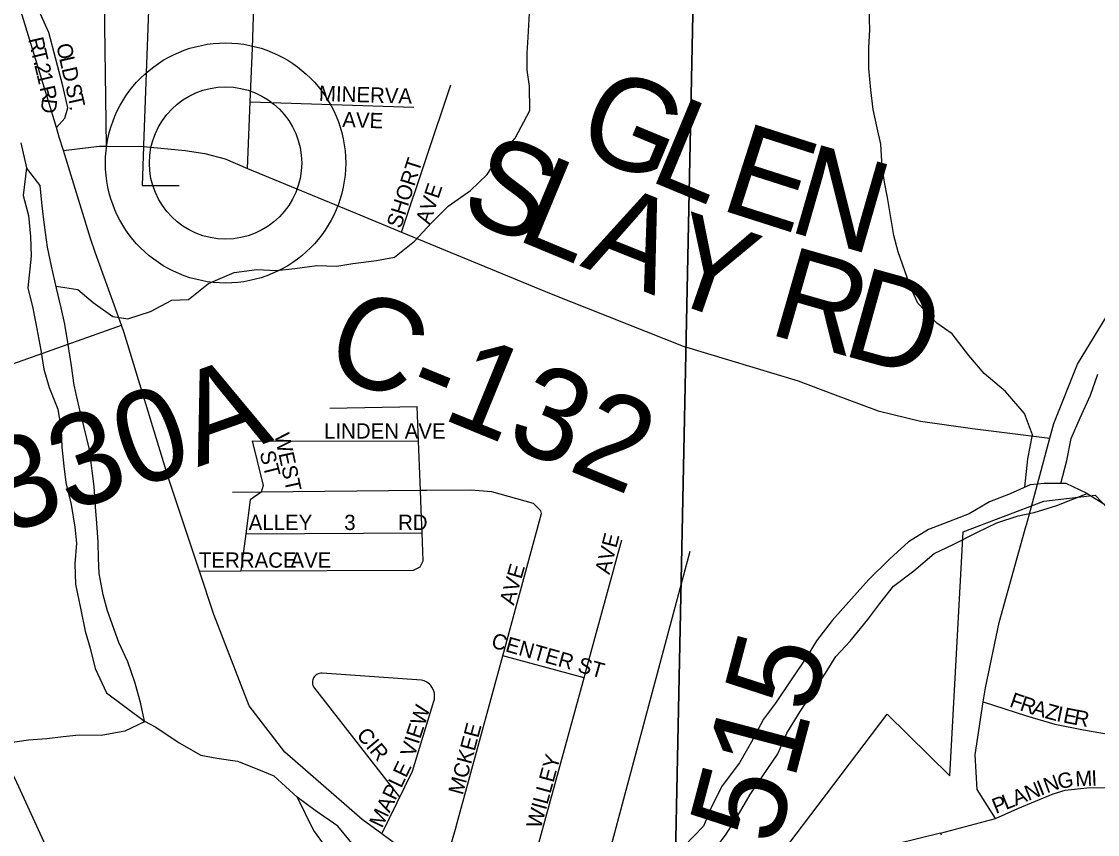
# Model space of a CAD drawing. Extents: x 2043100 to 2470832, y 443715 to 810583.
# Drawn here: x 2240142 to 2243660, y 639483 to 642142 of the extents above; entities that cross this region are included whole.
import ezdxf

# ---------------------------------------------------------------- set-up
doc = ezdxf.new("R2010")
doc.units = 0
for name, color, linetype in [('GM_X_City_Street', 7, 'Continuous'), ('GM_X_City_Street_Text', 7, 'Continuous'), ('GM_X_Corporation', 7, 'Continuous'), ('GM_X_County_Road', 7, 'Continuous'), ('GM_X_County_Road_Text', 7, 'Continuous'), ('GM_X_Interstate_Route', 7, 'Continuous'), ('GM_X_Major_River', 7, 'Continuous'), ('GM_X_Minor_River', 7, 'Continuous'), ('GM_X_Section', 7, 'Continuous'), ('GM_X_State_Route', 7, 'Continuous'), ('GM_X_Township_Road', 7, 'Continuous'), ('GM_X_Township_Road_Text', 7, 'Continuous'), ('GM_X_Township_Subdivision', 7, 'Continuous'), ('GM_X_Township_Subdivision_Text', 7, 'Continuous'), ('GM_X_Unincorporated', 7, 'Continuous'), ('GM_X_Unincorporated_Location', 7, 'Continuous')]:
    doc.layers.add(name, color=color, linetype=linetype)

msp = doc.modelspace()

# ---------------------------------------------------------------- linework, layer by layer
at = {"layer": 'GM_X_City_Street'}
for points in [[(2243286.7, 639917.5), (2243427.8, 639871.2), (2243520.1, 639844.4), (2243614.3, 639825.7), (2243753.1, 639801.8), (2244056.4, 639793.6), (2244190.2, 639793.3), (2244301.9, 639785.7), (2244380.2, 639763.3), (2244436.7, 639738.5), (2244587.8, 639642.4), (2244776.1, 639523.2)], [(2243326.2, 639536.1), (2243399.7, 639568.6), (2243515, 639616.2), (2243554.8, 639628.7), (2243624.7, 639635.6), (2243748.2, 639637.1)]]:
    msp.add_lwpolyline(points, dxfattribs=at)
at = {"layer": 'GM_X_Corporation'}
msp.add_lwpolyline([(2242944.3, 637149), (2242931.5, 637610.5), (2240814.2, 637621.4), (2240814.2, 638839.3), (2242113.9, 638816.9), (2242623.4, 639416.8), (2242972.5, 639877.1), (2243176.9, 639675.1), (2243220.7, 640473.4), (2243485, 640573.3), (2243652.8, 640592.9), (2243759.2, 640481)], dxfattribs=at)
at = {"layer": 'GM_X_County_Road'}
msp.add_lwpolyline([(2240278.9, 641720.1), (2240395.4, 641734.2), (2240419.4, 641734.3), (2240540.7, 641733.6), (2240677.3, 641720.6), (2240741.3, 641710.7), (2240807.3, 641692.8), (2240881.3, 641662.1), (2241235.3, 641515.2), (2241384.7, 641453.5), (2241873.3, 641251.9), (2242305.3, 641080.3), (2242681.2, 640966.7), (2242793.2, 640924.9), (2242943.2, 640869), (2243081.2, 640835.2), (2243251.2, 640811.4), (2243504.2, 640779.5)], dxfattribs=at)
at = {"layer": 'GM_X_Interstate_Route'}
msp.add_lwpolyline([(2240394.7, 638771), (2240382.5, 638881.1), (2240303.2, 639267.5), (2240121.4, 639665.5), (2239921.6, 640061.4), (2239486.5, 640666.7), (2238945.3, 641275.5), (2238484.4, 641836.6), (2237995, 642501.7), (2237789.2, 642869.6), (2237609.2, 643317.8), (2237341.9, 644058.2), (2237167.9, 644510.4), (2236925.2, 645114.6), (2236607.5, 645943), (2236281.8, 646755.3), (2236081.5, 647271.5), (2235837.1, 647771.5), (2235579.2, 648157.2), (2235141.7, 648882.8), (2234805.3, 649336.2), (2234488.5, 649938.1), (2234352.9, 650290.3), (2234278.2, 650792.6)], dxfattribs=at)
at = {"layer": 'GM_X_Major_River'}
for points in [[(2240139.7, 641745.3), (2240158.6, 641663.4)], [(2240158.6, 641663.4), (2240147.5, 641573.2), (2240164.2, 641507.4), (2240170.9, 641439.4), (2240173.5, 641375.4), (2240162.6, 641271.2), (2240179.2, 641205.3), (2240191.9, 641137.4), (2240204.6, 641067.5), (2240215.3, 641005.6), (2240231.9, 640945.7), (2240260.6, 640874), (2240271.3, 640808), (2240273.9, 640750), (2240280.5, 640688.1), (2240287, 640634.1), (2240303.8, 640562.2), (2240316.5, 640488.3), (2240321.1, 640436.3), (2240315.7, 640368.2), (2240318.4, 640302.2), (2240335.3, 640218.3), (2240350, 640148.4), (2240366.6, 640092.6), (2240383.2, 640026.7), (2240420, 639947.1), (2240543.9, 639853.9)], [(2240543.9, 639853.9), (2240532.4, 639910.2), (2240513.7, 639978.1), (2240489, 640047.9), (2240460.3, 640111.6), (2240423.3, 640215.3), (2240408.8, 640267.2), (2240396, 640337.1), (2240393.5, 640387.1), (2240393, 640439.1), (2240388.4, 640501.1), (2240383.8, 640555.1), (2240379.1, 640621.1), (2240372.6, 640673.1), (2240363.9, 640743), (2240347.2, 640814.9), (2240330.5, 640880.8), (2240313.8, 640952.6), (2240305.1, 641016.6), (2240294.4, 641086.5), (2240283.7, 641152.4), (2240271.2, 641206.3), (2240256.6, 641270.2), (2240239.8, 641342.1), (2240227.2, 641404), (2240216.5, 641475.9), (2240209.8, 641539.9), (2240203.1, 641605.9), (2240158.6, 641663.4)], [(2243626.2, 640598.5), (2243557.9, 640631.8), (2243485.2, 640631.8), (2243440, 640626.5), (2243374.3, 640597.7), (2243306.6, 640571), (2243241, 640532.2), (2243173.3, 640505.5), (2243107.6, 640480.7), (2243042, 640440), (2242980.6, 640385.3), (2242911.3, 640316.5), (2242856, 640253.8), (2242792.8, 640183.1), (2242741.5, 640116.5), (2242710, 640064.1), (2242658.8, 639989.5), (2242607.6, 639912.9), (2242568.1, 639860.4), (2242528.9, 639785.9), (2242489.6, 639717.5), (2242432.4, 639642.8), (2242399.1, 639576.4), (2242371.8, 639510), (2242308.5, 639445.3)], [(2242400.7, 639424.3), (2242446, 639484.8), (2242481.4, 639541.2), (2242524.7, 639613.8), (2242564.1, 639672.2), (2242615.3, 639746.8), (2242644.6, 639815.2), (2242687.8, 639885.8), (2242737.1, 639958.3), (2242770.5, 640010.7), (2242804, 640065.1), (2242851.4, 640115.7), (2242908.7, 640186.4), (2242948.1, 640238.8), (2242993.5, 640295.4), (2243059, 640346.1), (2243126.4, 640402.9), (2243188.1, 640431.6), (2243267.6, 640472.5), (2243331.3, 640503.2), (2243401, 640526), (2243452.9, 640536.5), (2243526.7, 640559.4), (2243626.2, 640598.5)], [(2243626.2, 640598.5), (2243692.6, 640557.2), (2243751.2, 640499.8), (2243811.8, 640442.4), (2243862.1, 640404.9), (2243914.2, 640393.5)], [(2240543.9, 639853.9), (2240581.1, 639834.7), (2240657.6, 639783.5), (2240728, 639742.3), (2240780.1, 639732.8), (2240848.1, 639723.6), (2240916.4, 639696.3), (2240966.6, 639674.8), (2241043.3, 639605.6)], [(2241043.3, 639605.6), (2241096.4, 639496.1), (2241134.9, 639444.5)], [(2241232.9, 639441.6), (2241176.2, 639511), (2241101.7, 639562.2), (2241043.3, 639605.6)]]:
    msp.add_lwpolyline(points, dxfattribs=at)
at = {"layer": 'GM_X_Minor_River'}
for points in [[(2243423, 640619), (2243432.2, 640711.9), (2243448, 640790), (2243421.8, 640860), (2243359.6, 640931.8), (2243289.4, 640991.6), (2243239.3, 641049.5), (2243185.1, 641121.3), (2243135, 641155.2), (2243072.8, 641221), (2243048.7, 641273), (2243030.5, 641326.9), (2243008.4, 641388.9), (2242994.2, 641442.9), (2242984, 641500.9), (2242973.8, 641566.9), (2242963.7, 641616.9), (2242955.5, 641666.9), (2242951.3, 641741), (2242939.2, 641795), (2242927, 641855), (2242918.8, 641919), (2242912.6, 641989), (2242912.4, 642057.1), (2242916.2, 642115.1), (2242914, 642185.2)], [(2240255.1, 641276.6), (2240325.8, 641265.6), (2240375.9, 641223.7), (2240440, 641177.9), (2240490, 641170.1), (2240563.9, 641194.4), (2240633.8, 641230.6), (2240687.7, 641232.8), (2240753.6, 641285.1), (2240837.4, 641321.4), (2240911.4, 641331.7), (2240975.3, 641327.9), (2241035.3, 641334.1), (2241107.2, 641344.3), (2241173.2, 641342.6), (2241225.2, 641350.8), (2241303.1, 641361), (2241361.1, 641371.2), (2241426.9, 641423.5), (2241482.7, 641483.7), (2241536.5, 641538), (2241610.3, 641590.2), (2241664.1, 641642.5), (2241698, 641694.6), (2241755.7, 641760.9), (2241803.5, 641851.1), (2241803.2, 641931.2), (2241795.1, 641983.2), (2241794.9, 642039.2), (2241798.7, 642091.3), (2241802.5, 642169.3)], [(2243540.3, 640631.8), (2243560.2, 640706.3), (2243573.9, 640778.4), (2243603.7, 640846.6), (2243637.5, 640920.7), (2243661.3, 640988.9)], [(2240546.6, 639852.5), (2240480.1, 639821.1), (2240402.1, 639806.8), (2240330.2, 639808.5), (2240278.2, 639802.4), (2240224.2, 639796.2), (2240164.3, 639792), (2240098.3, 639781.7)]]:
    msp.add_lwpolyline(points, dxfattribs=at)
at = {"layer": 'GM_X_Section'}
for points in [[(2242378.2, 644174.8), (2242269, 638887.7), (2242088.5, 638885.8), (2236986.2, 638960.8), (2237095.6, 644222)], [(2247636.8, 644123.4), (2247507.7, 638791.7), (2242269, 638887.7), (2242378.2, 644174.8)]]:
    msp.add_lwpolyline(points, close=True, dxfattribs=at)
at = {"layer": 'GM_X_State_Route'}
for points in [[(2240384.2, 641385), (2240367.1, 641432.7), (2240278.9, 641720.1), (2240265.4, 641764.1), (2240255.7, 641796.2), (2240129.1, 642214.4), (2239996.8, 642598.6), (2239934.5, 642755.4), (2239884.6, 642880.8), (2239654.4, 643240.8), (2239542.3, 643362.8), (2239348.2, 643548.7), (2239224.2, 643672.7), (2238711.9, 644192.5), (2238530.6, 644495.1), (2238493.7, 644556.6), (2238411.1, 644745.2), (2238269.4, 645068.8), (2238174.6, 645363.4), (2238086.8, 645787.4), (2237986.4, 646321.9), (2237949.9, 646434.6), (2237924.3, 646608.8)], [(2243427.3, 640494.3), (2243427.8, 640496), (2243447.7, 640567.6), (2243504.2, 640779.5), (2243517, 640827.8), (2243594.9, 641022.1), (2243746.6, 641270.6), (2243823.2, 641405.3), (2243897.3, 641485.5)], [(2241707.1, 639276.8), (2241672.9, 639289.4), (2241519.2, 639358.5), (2241446.4, 639391.3), (2241319.8, 639485.2), (2241255.9, 639532.6), (2241002.8, 639752.9), (2240885.8, 639903.7), (2240770.5, 640203.1), (2240723.5, 640344.6), (2240622.2, 640649.3), (2240477.8, 641123.7), (2240468.9, 641148.8), (2240384.2, 641385)], [(2243146.3, 639487.8), (2243326.2, 639536.1), (2243266.1, 639630.1), (2243260, 639744.2), (2243286.7, 639917.5), (2243293.7, 639963.5), (2243339, 640176.2), (2243427.3, 640494.3)], [(2243149.7, 639480.8), (2243146.3, 639487.8), (2242933.7, 639435.4), (2242868.4, 639419.3), (2242834.4, 639417.2), (2242825.2, 639418.8), (2242716.5, 639437.1), (2242617.1, 639441.3), (2242579.7, 639442.8)]]:
    msp.add_lwpolyline(points, dxfattribs=at)
at = {"layer": 'GM_X_Township_Road'}
for points in [[(2239548.4, 640822), (2240468.9, 641148.8)], [(2242004.5, 639200.5), (2242328.2, 640409.5)]]:
    msp.add_lwpolyline(points, dxfattribs=at)
at = {"layer": 'GM_X_Township_Subdivision'}
for points in [[(2240881.3, 641662.1), (2240889.9, 641879.4), (2240896.9, 642055.3), (2240901.8, 642193.5), (2240913.6, 642525.3), (2240924.9, 642845.7), (2240916.2, 642998.4), (2240858.2, 643197.8), (2240800, 643302.6), (2240712.6, 643436), (2240583.8, 643632.6), (2240577.7, 643660.7), (2240581.7, 643680.7), (2240617.7, 643706.8), (2240845.6, 643771.2), (2240953.5, 643781.4), (2241073.5, 643763.5)], [(2240255.7, 641796.2), (2240283.3, 641826.2), (2240293.3, 641860.2), (2240277.2, 641932.3), (2240231.1, 642106.4), (2240205.1, 642164.4), (2240191, 642202.8), (2240179, 642272.5), (2240186.8, 642572.9), (2240193, 642845.1)], [(2240419.4, 641734.3), (2240413.1, 642206.8), (2240404.5, 642859.4)], [(2240582.4, 642851.9), (2240558.4, 642209.4), (2240540.9, 641738.1)], [(2241384.7, 641453.5), (2241546, 641935.4)], [(2240889.9, 641879.4), (2241424.9, 641861.9)], [(2240540.9, 641738.1), (2240540.7, 641733.6), (2240535.9, 641606.3), (2240657.4, 641606.5)], [(2241150.3, 640878.1), (2241435.5, 640882.9)], [(2241448.5, 640546.3), (2241448.5, 640546.6), (2241446.1, 640608.6), (2241439.9, 640769.8), (2241435.5, 640882.9)], [(2240896.5, 640770.6), (2241439.9, 640769.8)], [(2240896.5, 640770.6), (2240931.5, 640624.7), (2240931.5, 640624.4)], [(2240931.5, 640624.4), (2240925.7, 640602.9), (2240925.7, 640602.9), (2240889.9, 640578.3), (2240875.3, 640466.7), (2240859.5, 640345.3)], [(2241563.2, 639509.3), (2241716.2, 640067.5), (2241841.8, 640533.7), (2241839.7, 640541.7), (2241815.6, 640565.5), (2241679.3, 640604.5), (2241611.3, 640610), (2241467.4, 640608.8), (2241446.1, 640608.6), (2240925.7, 640602.9), (2240831.7, 640601.8)], [(2240723.5, 640344.6), (2240859.5, 640345.3), (2241423.3, 640348.2), (2241445.2, 640358.3), (2241455, 640378.4), (2241451.5, 640470.4), (2241448.5, 640546.3)], [(2240875.3, 640466.7), (2241451.5, 640470.4)], [(2241988.8, 640024.6), (2242104.3, 640447.6)], [(2241981.1, 639996.2), (2241716.2, 640067.5)], [(2241519.2, 639358.5), (2241804.1, 639347.9), (2241981.1, 639996.2), (2241988.8, 640024.6)], [(2241319.8, 639485.2), (2241420, 639690.6), (2241489.9, 639919.1), (2241491.7, 639926.2), (2241492.6, 639934.3), (2241492.5, 639940.2), (2241491.7, 639945.8), (2241490.3, 639951.6), (2241488.4, 639957), (2241483.6, 639965.7), (2241479.8, 639970.8), (2241476.1, 639974.7), (2241471.9, 639978.3), (2241467.1, 639981.6), (2241463, 639983.9), (2241458.6, 639985.8), (2241454, 639987.3), (2241449.8, 639988.4), (2241124.5, 640011.1), (2241120.4, 640011), (2241116, 640010.2), (2241111.9, 640008.8), (2241107.9, 640006.8), (2241104.6, 640004.6), (2241101.7, 640001.9), (2241099.1, 639999), (2241096.9, 639995.6), (2241095.3, 639992.5), (2241094.1, 639988.8), (2241093.2, 639984.8), (2241092.9, 639980.4), (2241093.3, 639975.9), (2241094.5, 639970.8), (2241096.4, 639966.3), (2241099.5, 639961.6), (2241377.6, 639605.6)], [(2241548.5, 639459), (2241562.8, 639508), (2241563.2, 639509.3)]]:
    msp.add_lwpolyline(points, dxfattribs=at)
at = {"layer": 'GM_X_Unincorporated'}
for radius in [392.8, 249]:
    msp.add_circle((2240809, 641679.6), radius, dxfattribs=at)
at = {"layer": 'GM_X_Unincorporated_Location'}
msp.add_line((2240809, 641679.6), (2240809, 641679.6), dxfattribs=at)

# ---------------------------------------------------------------- texts
at = {"layer": 'GM_X_City_Street_Text'}
for s, rotation, p in [('F', 340.7615, (2243369.3, 639902.1)), ('R', 341.5004, (2243403.2, 639890.3)), ('A', 343.8673, (2243442.8, 639877)), ('Z', 344.87, (2243486, 639864.6)), ('I', 348.5074, (2243523.4, 639854.6)), ('E', 348.9555, (2243545.4, 639850.1)), ('R', 349.5121, (2243580.4, 639843.3)), ('N', 20.1493, (2243494.6, 639617.3)), ('G', 9.5953, (2243533.6, 639631.9)), ('M', 2.897, (2243588.6, 639640)), ('I', 2.6681, (2243641.3, 639642.7)), ('N', 21.9518, (2243433.8, 639592.8)), ('I', 21.9751, (2243474.6, 639609.3)), ('P', 21.9536, (2243327.7, 639550)), ('L', 21.9692, (2243360.3, 639563.2)), ('A', 21.9557, (2243393, 639576.4))]:
    msp.add_text(s, height=50, rotation=rotation, dxfattribs=at).set_placement(p)
at = {"layer": 'GM_X_County_Road_Text'}
for s, rotation, p in [('G', 337.4572, (2241942.5, 641726.3)), ('L', 337.4553, (2242186.3, 641625.1)), ('E', 342.2449, (2242419.2, 641529.6)), ('S', 337.4116, (2241565.7, 641509.8)), ('N', 343.9312, (2242642.2, 641458.4)), ('L', 337.4388, (2241752.8, 641432)), ('A', 338.3004, (2241964.6, 641344)), ('Y', 340.8863, (2242223.7, 641241.3)), ('R', 343.9988, (2242578.4, 641122.2)), ('D', 344.4572, (2242817.8, 641053.6)), ('C-132', 337.7418, (2241118.8, 641005.9))]:
    msp.add_text(s, height=300, rotation=rotation, dxfattribs=at).set_placement(p)
at = {"layer": 'GM_X_Township_Road_Text'}
for s, rotation, p in [('T-330A', 19.4643, (2239729.5, 640335.2)), ('T-515', 75.2139, (2242514.5, 639074.6))]:
    msp.add_text(s, height=300, rotation=rotation, dxfattribs=at).set_placement(p)
at = {"layer": 'GM_X_Township_Subdivision_Text'}
for s, rotation, p in [('R', 283.3059, (2240163.3, 642085.1)), ('O', 282.6473, (2240255.1, 642065.3)), ('T', 283.2875, (2240172.5, 642046.6)), ('.', 283.2879, (2240180.6, 642012.3)), ('2', 283.3069, (2240183.6, 641999.5)), ('L', 282.6676, (2240264.7, 642022.4)), ('D', 282.6473, (2240272.5, 641988)), ('1', 283.2638, (2240190.7, 641969.5)), ('R', 282.8818, (2240200.7, 641926.7)), ('S', 282.6676, (2240285, 641932.2)), ('MINERVA', 358.2386, (2241113.7, 641882.7)), ('T', 282.6444, (2240292.7, 641897.8)), ('D', 263.9567, (2240209.3, 641892.5)), ('.', 265.9144, (2240300.1, 641867.3)), ('AVE', 358.0261, (2241190, 641797.3)), ('SHORT', 72.3495, (2241382.2, 641463)), ('AVE', 71.5675, (2241476.5, 641475.7)), ('WEST', 282.1988, (2240968.3, 640790.6)), ('LINDEN AVE', 0, (2241131, 640778.3)), ('ST', 284.0427, (2240919.9, 640732.1)), ('ALLEY', 0, (2240884.6, 640479.1)), ('3', 0, (2241197, 640479.1)), ('RD', 0, (2241373, 640479.1)), ('AVE', 75.4658, (2242064.1, 640331.7)), ('TERRACE', 0, (2240721.8, 640355.9)), ('AVE', 0, (2241021, 640355.9)), ('AVE', 74.0556, (2241751.8, 640230.7)), ('CENTER ST', 344.2675, (2241674.6, 640096)), ('VIEW', 72.0698, (2241426.3, 639733.8)), ('MCKEE', 74.8455, (2241584.5, 639610.2)), ('CIR', 309.808, (2241234.6, 639807.1)), ('WILLEY', 74.6506, (2241839.7, 639500.2)), ('MAPLE', 64.536, (2241321.1, 639501.7))]:
    msp.add_text(s, height=50, rotation=rotation, dxfattribs=at).set_placement(p)

doc.saveas('drawing.dxf')
